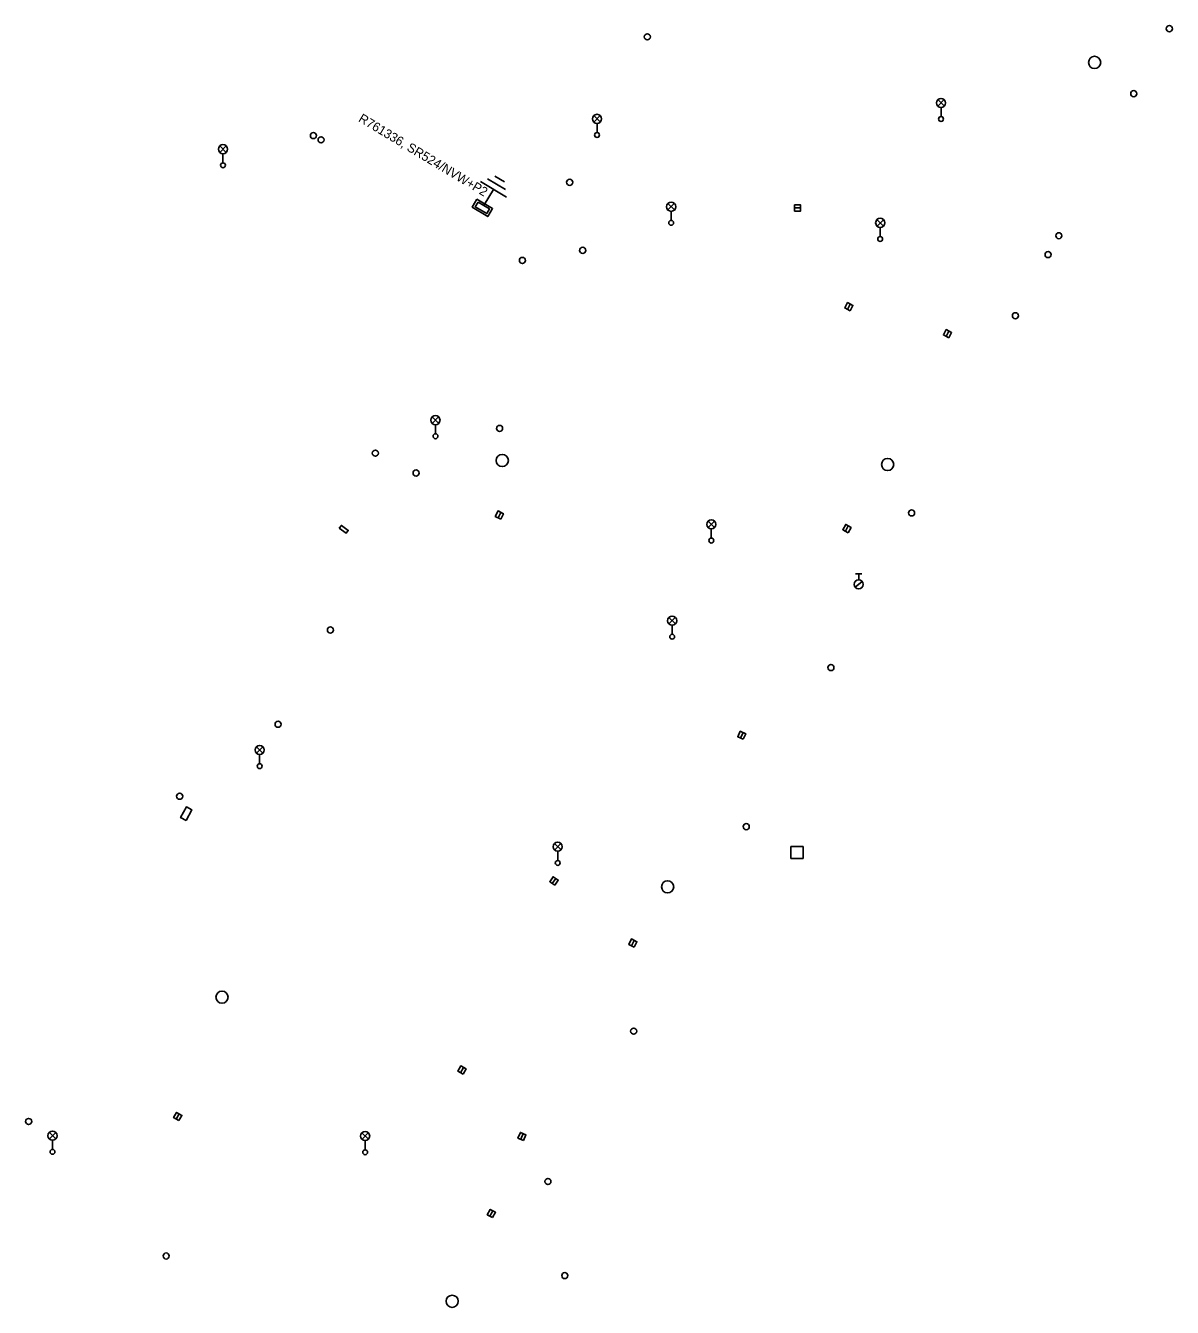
# Model space of a CAD drawing. Extents: x -577028 to -568584, y -1207664 to -1202947.
# Drawn here: x -568774.1 to -568679.9, y -1203841.2 to -1203735.9 of the extents above; entities that cross this region are included whole.
import ezdxf

# ---------------------------------------------------------------- set-up
doc = ezdxf.new("R2010")
doc.units = 0
for name, color, linetype in [('CIZÍ_NADZEM', 7, 'Continuous'), ('ELE_EON', 7, 'Continuous'), ('ELE_EON_POPIS', 7, 'Continuous')]:
    doc.layers.add(name, color=color, linetype=linetype)

msp = doc.modelspace()

# ---------------------------------------------------------------- linework, layer by layer
at = {"layer": 'CIZÍ_NADZEM'}
for p, q in [((-568699.16, -1203742.47), (-568698.64, -1203741.94)), ((-568698.63, -1203742.47), (-568699.16, -1203741.94)), ((-568698.9, -1203742.58), (-568698.9, -1203743.33)), ((-568727.43, -1203743.78), (-568726.91, -1203743.25)), ((-568726.9, -1203743.78), (-568727.43, -1203743.25)), ((-568727.17, -1203743.89), (-568727.17, -1203744.64)), ((-568758.17, -1203746.27), (-568757.65, -1203745.74)), ((-568757.64, -1203746.27), (-568758.17, -1203745.74)), ((-568757.91, -1203746.38), (-568757.91, -1203747.13)), ((-568721.34, -1203751), (-568720.82, -1203750.47)), ((-568720.81, -1203751), (-568721.34, -1203750.47)), ((-568710.94, -1203750.84), (-568710.44, -1203750.84)), ((-568721.08, -1203751.11), (-568721.08, -1203751.86)), ((-568704.16, -1203752.33), (-568703.64, -1203751.8)), ((-568703.63, -1203752.32), (-568704.16, -1203751.8)), ((-568703.9, -1203752.44), (-568703.9, -1203753.19)), ((-568706.6, -1203759.17), (-568706.36, -1203758.73)), ((-568698.49, -1203761.39), (-568698.25, -1203760.95)), ((-568740.71, -1203768.53), (-568740.19, -1203768)), ((-568740.18, -1203768.53), (-568740.71, -1203768)), ((-568740.45, -1203768.64), (-568740.45, -1203769.39)), ((-568735.31, -1203776.29), (-568735.09, -1203775.85)), ((-568718.04, -1203777.1), (-568717.52, -1203776.57)), ((-568717.51, -1203777.09), (-568718.04, -1203776.57)), ((-568717.78, -1203777.21), (-568717.78, -1203777.96)), ((-568706.76, -1203777.4), (-568706.52, -1203776.96)), ((-568705.96, -1203781.99), (-568705.37, -1203781.53)), ((-568705.92, -1203780.89), (-568705.42, -1203780.89)), ((-568705.67, -1203781.39), (-568705.67, -1203780.89)), ((-568721.26, -1203785), (-568720.74, -1203784.47)), ((-568720.73, -1203785), (-568721.26, -1203784.47)), ((-568721, -1203785.11), (-568721, -1203785.86)), ((-568715.39, -1203794.38), (-568715.17, -1203793.92)), ((-568755.16, -1203795.63), (-568754.64, -1203795.1)), ((-568754.63, -1203795.62), (-568755.16, -1203795.1)), ((-568754.9, -1203795.74), (-568754.9, -1203796.49)), ((-568730.66, -1203803.58), (-568730.14, -1203803.05)), ((-568730.13, -1203803.57), (-568730.66, -1203803.05)), ((-568730.4, -1203803.69), (-568730.4, -1203804.44)), ((-568710.24, -1203803.29), (-568711.24, -1203803.29)), ((-568711.24, -1203803.29), (-568711.24, -1203804.29)), ((-568710.24, -1203804.29), (-568710.24, -1203803.29)), ((-568711.24, -1203804.29), (-568710.24, -1203804.29)), ((-568730.85, -1203806.33), (-568730.57, -1203805.91)), ((-568724.35, -1203811.44), (-568724.11, -1203811)), ((-568738.39, -1203821.88), (-568738.15, -1203821.44)), ((-568761.76, -1203825.69), (-568761.5, -1203825.25)), ((-568772.18, -1203827.31), (-568771.66, -1203826.78)), ((-568771.65, -1203827.31), (-568772.18, -1203826.78)), ((-568746.49, -1203827.35), (-568745.97, -1203826.82)), ((-568745.96, -1203827.34), (-568746.49, -1203826.82)), ((-568733.44, -1203827.34), (-568733.24, -1203826.88)), ((-568771.92, -1203827.42), (-568771.92, -1203828.17)), ((-568746.23, -1203827.46), (-568746.23, -1203828.21)), ((-568735.97, -1203833.66), (-568735.73, -1203833.22))]:
    msp.add_line(p, q, dxfattribs=at)
for points in [[(-568710.94, -1203751.09), (-568710.44, -1203751.09), (-568710.44, -1203750.59), (-568710.94, -1203750.59)], [(-568706.38, -1203759.29), (-568706.14, -1203758.85), (-568706.58, -1203758.61), (-568706.82, -1203759.05)], [(-568698.27, -1203761.51), (-568698.03, -1203761.07), (-568698.47, -1203760.83), (-568698.71, -1203761.27)], [(-568735.09, -1203776.41), (-568734.86, -1203775.96), (-568735.31, -1203775.73), (-568735.54, -1203776.18)], [(-568706.54, -1203777.52), (-568706.3, -1203777.09), (-568706.73, -1203776.84), (-568706.98, -1203777.27)], [(-568715.16, -1203794.48), (-568714.95, -1203794.03), (-568715.4, -1203793.82), (-568715.61, -1203794.27)], [(-568730.64, -1203806.47), (-568730.36, -1203806.05), (-568730.78, -1203805.77), (-568731.06, -1203806.19)], [(-568724.12, -1203811.56), (-568723.89, -1203811.11), (-568724.34, -1203810.88), (-568724.57, -1203811.33)], [(-568738.17, -1203822), (-568737.93, -1203821.56), (-568738.37, -1203821.32), (-568738.61, -1203821.76)], [(-568761.54, -1203825.81), (-568761.29, -1203825.38), (-568761.72, -1203825.13), (-568761.97, -1203825.56)], [(-568733.21, -1203827.44), (-568733.01, -1203826.98), (-568733.47, -1203826.78), (-568733.67, -1203827.24)], [(-568735.75, -1203833.78), (-568735.51, -1203833.34), (-568735.95, -1203833.1), (-568736.19, -1203833.54)]]:
    msp.add_lwpolyline(points, close=True, dxfattribs=at)
for points in [[(-568748.36, -1203777.15), (-568747.8, -1203777.56), (-568747.62, -1203777.32), (-568748.18, -1203776.91), (-568748.36, -1203777.15)], [(-568760.95, -1203801.15), (-568760.48, -1203800.27), (-568760.92, -1203800.04), (-568761.39, -1203800.92), (-568760.95, -1203801.15)]]:
    msp.add_lwpolyline(points, dxfattribs=at)
for centre, radius in [((-568680.14, -1203736.11), 0.25), ((-568723.04, -1203736.78), 0.25), ((-568686.28, -1203738.88), 0.5), ((-568683.06, -1203741.45), 0.25), ((-568698.9, -1203742.21), 0.375), ((-568727.17, -1203743.52), 0.375), ((-568698.9, -1203743.53), 0.2), ((-568750.48, -1203744.89), 0.25), ((-568727.17, -1203744.84), 0.2), ((-568757.91, -1203746.01), 0.375), ((-568749.85, -1203745.24), 0.25), ((-568757.91, -1203747.33), 0.2), ((-568729.42, -1203748.73), 0.25), ((-568721.08, -1203750.74), 0.375), ((-568721.08, -1203752.06), 0.2), ((-568703.9, -1203752.06), 0.375), ((-568703.9, -1203753.39), 0.2), ((-568689.22, -1203753.12), 0.25), ((-568728.35, -1203754.32), 0.25), ((-568733.3, -1203755.15), 0.25), ((-568690.1, -1203754.67), 0.25), ((-568692.79, -1203759.69), 0.25), ((-568740.45, -1203768.27), 0.375), ((-568735.18, -1203768.95), 0.25), ((-568740.45, -1203769.59), 0.2), ((-568745.39, -1203770.98), 0.25), ((-568734.96, -1203771.58), 0.5), ((-568703.29, -1203771.91), 0.5), ((-568742.04, -1203772.61), 0.25), ((-568701.32, -1203775.89), 0.25), ((-568717.78, -1203776.83), 0.375), ((-568717.78, -1203778.16), 0.2), ((-568705.67, -1203781.76), 0.375), ((-568721, -1203784.74), 0.375), ((-568749.08, -1203785.51), 0.25), ((-568721, -1203786.06), 0.2), ((-568707.95, -1203788.59), 0.25), ((-568753.38, -1203793.25), 0.25), ((-568754.9, -1203795.36), 0.375), ((-568754.9, -1203796.69), 0.2), ((-568761.47, -1203799.16), 0.25), ((-568714.91, -1203801.66), 0.25), ((-568730.4, -1203803.31), 0.375), ((-568730.4, -1203804.64), 0.2), ((-568721.37, -1203806.61), 0.5), ((-568757.99, -1203815.67), 0.5), ((-568724.16, -1203818.46), 0.25), ((-568773.88, -1203825.88), 0.25), ((-568771.92, -1203827.05), 0.375), ((-568746.23, -1203827.08), 0.375), ((-568771.92, -1203828.37), 0.2), ((-568746.23, -1203828.41), 0.2), ((-568731.21, -1203830.81), 0.25), ((-568762.58, -1203836.93), 0.25), ((-568729.82, -1203838.54), 0.25), ((-568739.07, -1203840.65), 0.5)]:
    msp.add_circle(centre, radius, dxfattribs=at)
at = {"layer": 'ELE_EON'}
for p, q in [((-568734.61, -1203749.95), (-568736.76, -1203748.66)), ((-568734.7, -1203749.31), (-568736.16, -1203748.44)), ((-568734.78, -1203748.68), (-568735.56, -1203748.22)), ((-568735.68, -1203749.31), (-568736.46, -1203750.59))]:
    msp.add_line(p, q, dxfattribs=at)
for points in [[(-568737.05, -1203750.12), (-568735.76, -1203750.89), (-568736.15, -1203751.54), (-568737.43, -1203750.76)], [(-568736.95, -1203750.35), (-568736.01, -1203750.92), (-568736.24, -1203751.3), (-568737.18, -1203750.74)]]:
    msp.add_lwpolyline(points, close=True, dxfattribs=at)

# ---------------------------------------------------------------- texts
at = {"layer": 'ELE_EON_POPIS'}
msp.add_text('R761336, SR524/NVW+P2', height=0.75, rotation=329.0363, dxfattribs=at).set_placement((-568746.84, -1203743.69))

doc.saveas('drawing.dxf')
